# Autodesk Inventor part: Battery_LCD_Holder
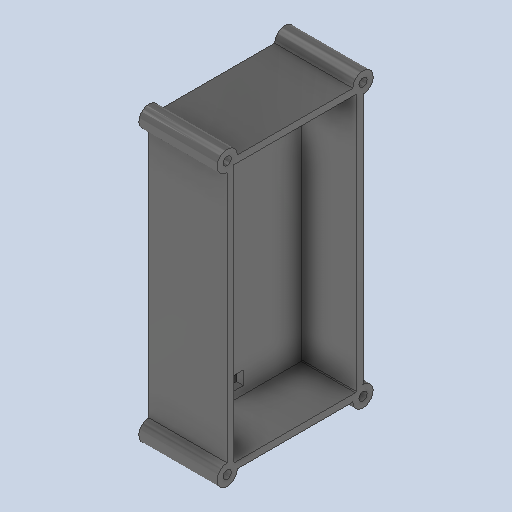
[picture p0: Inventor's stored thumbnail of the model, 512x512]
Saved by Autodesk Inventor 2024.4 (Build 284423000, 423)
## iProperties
Created: 2025-05
Part Number: Battery_LCD_Holder
Material: Generic
Document SubType Name: Modeling
Designer: AdminForWorker
Density: 1 g/cm^3
Appearance: Default
Title: Battery_LCD_Holder
Author: AdminForWorker
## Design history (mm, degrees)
feature "Body1"
body "Solid1"
